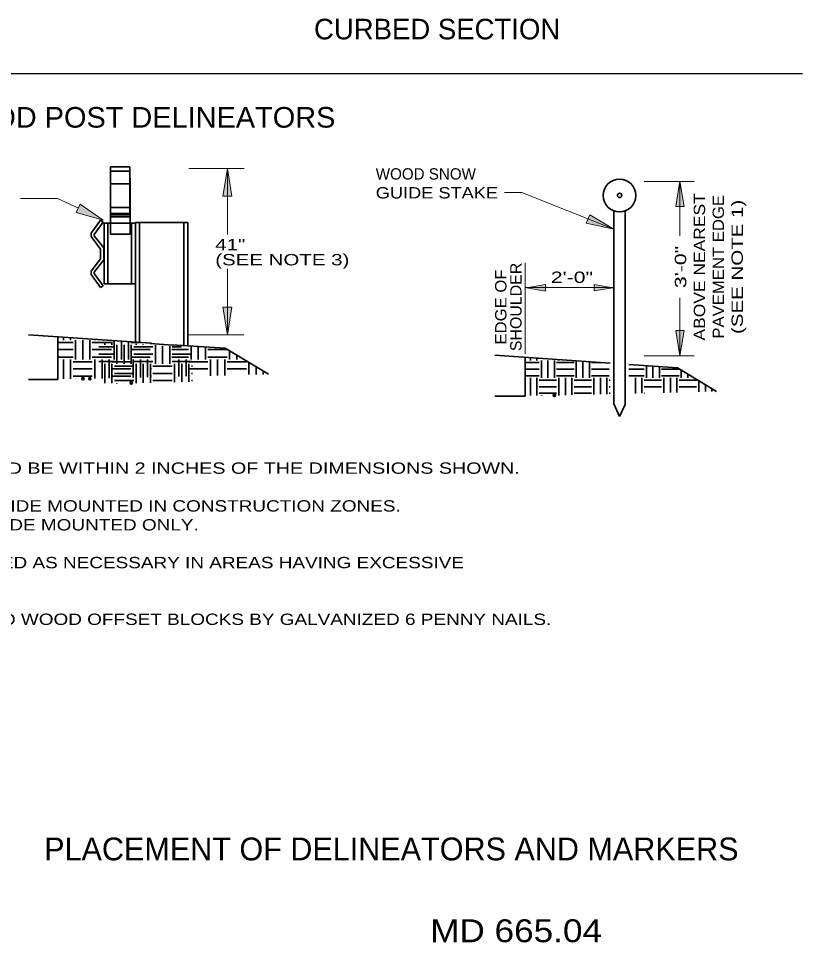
# Model space of a CAD drawing. Extents: x 2147527.1 to 2147534.3, y 2147768.5 to 2147778.6.
# Drawn here: x 2147530.091 to 2147534.243, y 2147768.504 to 2147773.395 of the extents above; entities that cross this region are included whole.
import ezdxf
from ezdxf.enums import TextEntityAlignment as Align

# ---------------------------------------------------------------- set-up
doc = ezdxf.new("R2010")
doc.units = 0
doc.header["$LTSCALE"] = 0.024
doc.header["$PDMODE"] = 32
doc.header["$PDSIZE"] = 0.012
for name, color, linetype, lineweight in [('1', 7, 'Continuous', 35), ('10', 7, 'Continuous', 13), ('63', 7, 'Continuous', 35)]:
    doc.layers.add(name, color=color, linetype=linetype, lineweight=lineweight)
doc.layers.add('12', color=7, linetype='Continuous')
doc.layers.add('13', color=7, linetype='Continuous')

msp = doc.modelspace()

# ---------------------------------------------------------------- hatches: boundary and pattern name
at = {"layer": '10'}
for points in [[(2147531.221, 2147772.454), (2147531.173, 2147772.454), (2147531.197, 2147772.6)], [(2147533.616, 2147772.4), (2147533.572, 2147772.4), (2147533.594, 2147772.533)], [(2147530.397, 2147772.367), (2147530.418, 2147772.412), (2147530.54, 2147772.327)], [(2147533.098, 2147772.311), (2147533.116, 2147772.356), (2147533.243, 2147772.279)], [(2147532.882, 2147771.952), (2147532.882, 2147771.986), (2147532.782, 2147771.969)], [(2147533.139, 2147771.953), (2147533.139, 2147771.986), (2147533.239, 2147771.969)], [(2147531.221, 2147771.866), (2147531.173, 2147771.866), (2147531.197, 2147771.72)], [(2147533.616, 2147771.743), (2147533.572, 2147771.743), (2147533.594, 2147771.61)]]:
    msp.add_hatch(color=256, dxfattribs=at).paths.add_polyline_path(points)

# ---------------------------------------------------------------- linework, layer by layer
at = {"layer": '1'}
for p, q in [((2147530.578, 2147772.61), (2147530.578, 2147772.345)), ((2147530.578, 2147772.61), (2147530.681, 2147772.61)), ((2147530.681, 2147772.587), (2147530.578, 2147772.587)), ((2147530.681, 2147772.345), (2147530.681, 2147772.61)), ((2147530.578, 2147772.254), (2147530.578, 2147772.549)), ((2147530.578, 2147772.519), (2147530.682, 2147772.519)), ((2147530.682, 2147772.549), (2147530.682, 2147772.254)), ((2147530.578, 2147772.394), (2147530.681, 2147772.394)), ((2147533.243, 2147772.377), (2147533.243, 2147771.355)), ((2147533.303, 2147772.377), (2147533.303, 2147771.351)), ((2147530.526, 2147772.327), (2147530.54, 2147772.317)), ((2147530.578, 2147772.362), (2147530.682, 2147772.362)), ((2147530.578, 2147772.356), (2147530.682, 2147772.356)), ((2147530.578, 2147772.344), (2147530.682, 2147772.344)), ((2147530.545, 2147772.314), (2147530.544, 2147771.991)), ((2147530.71, 2147772.311), (2147530.545, 2147772.311)), ((2147530.565, 2147772.314), (2147530.564, 2147771.991)), ((2147530.69, 2147772.313), (2147530.69, 2147771.99)), ((2147530.71, 2147772.314), (2147530.71, 2147771.682)), ((2147530.71, 2147772.314), (2147530.766, 2147772.314)), ((2147530.71, 2147772.313), (2147530.71, 2147771.99)), ((2147530.731, 2147772.314), (2147530.731, 2147771.68)), ((2147530.735, 2147772.314), (2147530.925, 2147772.314)), ((2147530.926, 2147772.314), (2147530.987, 2147772.314)), ((2147530.967, 2147772.314), (2147530.967, 2147771.664)), ((2147530.987, 2147772.314), (2147530.987, 2147771.662)), ((2147530.682, 2147772.254), (2147530.578, 2147772.254)), ((2147530.526, 2147772.123), (2147530.526, 2147772.149)), ((2147530.543, 2147772.117), (2147530.543, 2147772.149)), ((2147530.476, 2147772.057), (2147530.526, 2147772.123)), ((2147530.492, 2147772.052), (2147530.543, 2147772.117)), ((2147530.476, 2147772.039), (2147530.476, 2147772.057)), ((2147530.526, 2147771.97), (2147530.476, 2147772.039)), ((2147530.492, 2147772.045), (2147530.492, 2147772.052)), ((2147530.54, 2147771.98), (2147530.492, 2147772.045)), ((2147530.71, 2147771.99), (2147530.544, 2147771.991)), ((2147530.54, 2147771.98), (2147530.526, 2147771.97)), ((2147530.144, 2147771.721), (2147530.795, 2147771.676)), ((2147530.299, 2147771.71), (2147530.299, 2147771.484)), ((2147530.33, 2147771.692), (2147530.33, 2147771.708)), ((2147530.367, 2147771.692), (2147530.367, 2147771.705)), ((2147530.393, 2147771.59), (2147530.393, 2147771.692)), ((2147530.432, 2147771.59), (2147530.432, 2147771.692)), ((2147530.469, 2147771.59), (2147530.469, 2147771.692)), ((2147530.495, 2147771.692), (2147530.495, 2147771.696)), ((2147530.534, 2147771.692), (2147530.534, 2147771.694)), ((2147530.597, 2147771.59), (2147530.597, 2147771.69)), ((2147530.299, 2147771.68), (2147530.38, 2147771.68)), ((2147530.299, 2147771.642), (2147530.38, 2147771.642)), ((2147530.482, 2147771.68), (2147530.584, 2147771.68)), ((2147530.482, 2147771.642), (2147530.584, 2147771.642)), ((2147530.517, 2147771.656), (2147530.599, 2147771.656)), ((2147530.548, 2147771.668), (2147530.548, 2147771.684)), ((2147530.586, 2147771.668), (2147530.586, 2147771.682)), ((2147530.612, 2147771.567), (2147530.612, 2147771.668)), ((2147530.636, 2147771.59), (2147530.636, 2147771.686)), ((2147530.65, 2147771.567), (2147530.65, 2147771.668)), ((2147530.673, 2147771.59), (2147530.673, 2147771.684)), ((2147530.686, 2147771.68), (2147530.737, 2147771.68)), ((2147530.686, 2147771.642), (2147530.788, 2147771.642)), ((2147530.688, 2147771.567), (2147530.688, 2147771.668)), ((2147530.701, 2147771.656), (2147530.803, 2147771.656)), ((2147530.714, 2147771.668), (2147530.714, 2147771.673)), ((2147530.752, 2147771.668), (2147530.752, 2147771.67)), ((2147530.788, 2147771.675), (2147530.909, 2147771.666)), ((2147530.816, 2147771.567), (2147530.816, 2147771.666)), ((2147530.854, 2147771.567), (2147530.854, 2147771.663)), ((2147530.892, 2147771.567), (2147530.892, 2147771.66)), ((2147530.903, 2147771.668), (2147531.186, 2147771.649)), ((2147530.903, 2147771.642), (2147530.992, 2147771.642)), ((2147530.905, 2147771.656), (2147530.955, 2147771.656)), ((2147531.005, 2147771.59), (2147531.005, 2147771.661)), ((2147531.043, 2147771.59), (2147531.043, 2147771.659)), ((2147531.081, 2147771.59), (2147531.081, 2147771.656)), ((2147531.094, 2147771.642), (2147531.196, 2147771.642)), ((2147531.186, 2147771.649), (2147531.415, 2147771.512)), ((2147530.299, 2147771.603), (2147530.38, 2147771.603)), ((2147530.33, 2147771.488), (2147530.33, 2147771.59)), ((2147530.367, 2147771.488), (2147530.367, 2147771.59)), ((2147530.482, 2147771.603), (2147530.584, 2147771.603)), ((2147530.495, 2147771.489), (2147530.495, 2147771.59)), ((2147530.517, 2147771.618), (2147530.599, 2147771.618)), ((2147530.534, 2147771.49), (2147530.534, 2147771.59)), ((2147530.571, 2147771.491), (2147530.571, 2147771.59)), ((2147530.686, 2147771.603), (2147530.788, 2147771.603)), ((2147530.699, 2147771.494), (2147530.699, 2147771.59)), ((2147530.701, 2147771.618), (2147530.803, 2147771.618)), ((2147530.738, 2147771.495), (2147530.738, 2147771.59)), ((2147530.775, 2147771.496), (2147530.775, 2147771.59)), ((2147530.903, 2147771.603), (2147530.992, 2147771.603)), ((2147530.905, 2147771.618), (2147531.007, 2147771.618)), ((2147530.941, 2147771.5), (2147530.941, 2147771.59)), ((2147530.979, 2147771.501), (2147530.979, 2147771.59)), ((2147531.094, 2147771.603), (2147531.196, 2147771.603)), ((2147531.107, 2147771.504), (2147531.107, 2147771.59)), ((2147531.145, 2147771.505), (2147531.145, 2147771.59)), ((2147531.183, 2147771.506), (2147531.183, 2147771.59)), ((2147531.209, 2147771.59), (2147531.209, 2147771.635)), ((2147531.247, 2147771.59), (2147531.247, 2147771.612)), ((2147532.614, 2147771.612), (2147533.225, 2147771.57)), ((2147532.774, 2147771.601), (2147532.774, 2147771.396)), ((2147532.802, 2147771.585), (2147532.802, 2147771.599)), ((2147532.836, 2147771.585), (2147532.836, 2147771.597)), ((2147530.38, 2147771.578), (2147530.482, 2147771.578)), ((2147530.517, 2147771.58), (2147530.599, 2147771.58)), ((2147530.548, 2147771.465), (2147530.548, 2147771.567)), ((2147530.584, 2147771.578), (2147530.686, 2147771.578)), ((2147530.586, 2147771.465), (2147530.586, 2147771.567)), ((2147530.599, 2147771.554), (2147530.701, 2147771.554)), ((2147530.701, 2147771.58), (2147530.803, 2147771.58)), ((2147530.714, 2147771.465), (2147530.714, 2147771.567)), ((2147530.752, 2147771.466), (2147530.752, 2147771.567)), ((2147530.788, 2147771.578), (2147530.795, 2147771.578)), ((2147530.79, 2147771.467), (2147530.79, 2147771.567)), ((2147530.803, 2147771.554), (2147530.905, 2147771.554)), ((2147530.905, 2147771.58), (2147531.007, 2147771.58)), ((2147530.918, 2147771.47), (2147530.918, 2147771.567)), ((2147530.956, 2147771.471), (2147530.956, 2147771.567)), ((2147530.992, 2147771.578), (2147531.094, 2147771.578)), ((2147530.994, 2147771.472), (2147530.994, 2147771.567)), ((2147531.007, 2147771.554), (2147531.013, 2147771.554)), ((2147531.196, 2147771.578), (2147531.298, 2147771.578)), ((2147531.311, 2147771.51), (2147531.311, 2147771.574)), ((2147531.349, 2147771.51), (2147531.349, 2147771.551)), ((2147532.774, 2147771.574), (2147532.848, 2147771.574)), ((2147532.86, 2147771.492), (2147532.86, 2147771.585)), ((2147532.895, 2147771.492), (2147532.895, 2147771.585)), ((2147532.929, 2147771.492), (2147532.929, 2147771.585)), ((2147532.941, 2147771.574), (2147533.033, 2147771.574)), ((2147532.953, 2147771.585), (2147532.953, 2147771.589)), ((2147532.987, 2147771.585), (2147532.987, 2147771.586)), ((2147533.045, 2147771.492), (2147533.045, 2147771.583)), ((2147533.08, 2147771.492), (2147533.08, 2147771.58)), ((2147533.114, 2147771.492), (2147533.114, 2147771.578)), ((2147533.126, 2147771.574), (2147533.172, 2147771.574)), ((2147533.323, 2147771.563), (2147533.581, 2147771.545)), ((2147533.416, 2147771.492), (2147533.416, 2147771.557)), ((2147533.451, 2147771.492), (2147533.451, 2147771.555)), ((2147533.485, 2147771.492), (2147533.485, 2147771.552)), ((2147533.581, 2147771.545), (2147533.788, 2147771.421)), ((2147530.38, 2147771.54), (2147530.482, 2147771.54)), ((2147530.38, 2147771.501), (2147530.482, 2147771.501)), ((2147530.584, 2147771.54), (2147530.686, 2147771.54)), ((2147530.584, 2147771.501), (2147530.686, 2147771.501)), ((2147530.599, 2147771.516), (2147530.701, 2147771.516)), ((2147530.788, 2147771.54), (2147530.795, 2147771.54)), ((2147530.788, 2147771.501), (2147530.795, 2147771.501)), ((2147530.803, 2147771.516), (2147530.905, 2147771.516)), ((2147530.992, 2147771.54), (2147531.094, 2147771.54)), ((2147530.992, 2147771.501), (2147530.994, 2147771.501)), ((2147531.007, 2147771.516), (2147531.013, 2147771.516)), ((2147531.196, 2147771.54), (2147531.298, 2147771.54)), ((2147531.386, 2147771.511), (2147531.386, 2147771.528)), ((2147532.774, 2147771.539), (2147532.848, 2147771.539)), ((2147532.774, 2147771.504), (2147532.848, 2147771.504)), ((2147532.802, 2147771.4), (2147532.802, 2147771.492)), ((2147532.836, 2147771.4), (2147532.836, 2147771.492)), ((2147532.941, 2147771.539), (2147533.033, 2147771.539)), ((2147532.941, 2147771.504), (2147533.033, 2147771.504)), ((2147532.953, 2147771.4), (2147532.953, 2147771.492)), ((2147532.987, 2147771.401), (2147532.987, 2147771.492)), ((2147533.022, 2147771.402), (2147533.022, 2147771.492)), ((2147533.126, 2147771.539), (2147533.219, 2147771.539)), ((2147533.126, 2147771.504), (2147533.219, 2147771.504)), ((2147533.138, 2147771.405), (2147533.138, 2147771.492)), ((2147533.173, 2147771.406), (2147533.173, 2147771.492)), ((2147533.207, 2147771.406), (2147533.207, 2147771.492)), ((2147533.323, 2147771.539), (2147533.404, 2147771.539)), ((2147533.323, 2147771.504), (2147533.404, 2147771.504)), ((2147533.358, 2147771.41), (2147533.358, 2147771.492)), ((2147533.392, 2147771.412), (2147533.392, 2147771.492)), ((2147533.497, 2147771.539), (2147533.589, 2147771.539)), ((2147533.497, 2147771.504), (2147533.589, 2147771.504)), ((2147533.508, 2147771.414), (2147533.508, 2147771.492)), ((2147533.543, 2147771.415), (2147533.543, 2147771.492)), ((2147533.577, 2147771.416), (2147533.577, 2147771.492)), ((2147533.601, 2147771.492), (2147533.601, 2147771.533)), ((2147533.636, 2147771.492), (2147533.636, 2147771.512)), ((2147530.299, 2147771.484), (2147530.144, 2147771.484)), ((2147530.393, 2147771.487), (2147530.393, 2147771.488)), ((2147530.599, 2147771.478), (2147530.701, 2147771.478)), ((2147530.612, 2147771.463), (2147530.612, 2147771.465)), ((2147530.65, 2147771.464), (2147530.65, 2147771.465)), ((2147530.803, 2147771.478), (2147530.905, 2147771.478)), ((2147531.007, 2147771.478), (2147531.013, 2147771.478)), ((2147532.848, 2147771.481), (2147532.941, 2147771.481)), ((2147532.848, 2147771.446), (2147532.941, 2147771.446)), ((2147533.033, 2147771.481), (2147533.126, 2147771.481)), ((2147533.033, 2147771.446), (2147533.126, 2147771.446)), ((2147533.219, 2147771.481), (2147533.225, 2147771.481)), ((2147533.219, 2147771.446), (2147533.225, 2147771.446)), ((2147533.404, 2147771.481), (2147533.497, 2147771.481)), ((2147533.404, 2147771.446), (2147533.497, 2147771.446)), ((2147533.589, 2147771.481), (2147533.682, 2147771.481)), ((2147533.589, 2147771.446), (2147533.682, 2147771.446)), ((2147533.694, 2147771.419), (2147533.694, 2147771.477)), ((2147533.729, 2147771.42), (2147533.729, 2147771.457)), ((2147532.774, 2147771.396), (2147532.614, 2147771.396)), ((2147532.848, 2147771.412), (2147532.941, 2147771.412)), ((2147532.86, 2147771.398), (2147532.86, 2147771.4)), ((2147532.895, 2147771.399), (2147532.895, 2147771.4)), ((2147533.033, 2147771.412), (2147533.126, 2147771.412)), ((2147533.219, 2147771.412), (2147533.225, 2147771.412)), ((2147533.404, 2147771.412), (2147533.406, 2147771.412)), ((2147533.763, 2147771.42), (2147533.763, 2147771.436)), ((2147533.243, 2147771.355), (2147533.274, 2147771.288)), ((2147533.274, 2147771.288), (2147533.303, 2147771.351))]:
    msp.add_line(p, q, dxfattribs=at)
at = {"layer": '1', "lineweight": 13}
msp.add_line((2147530.992, 2147771.72), (2147531.285, 2147771.72), dxfattribs=at)
at = {"layer": '1'}
for points in [[(2147530.526, 2147772.327), (2147530.476, 2147772.258), (2147530.476, 2147772.24), (2147530.526, 2147772.174), (2147530.526, 2147772.149)], [(2147530.54, 2147772.317), (2147530.492, 2147772.252), (2147530.492, 2147772.245), (2147530.543, 2147772.18), (2147530.543, 2147772.149)]]:
    msp.add_lwpolyline(points, dxfattribs=at)
for radius in [0.0864, 0.0114]:
    msp.add_circle((2147533.2739, 2147772.4579), radius, dxfattribs=at)
for p in [(2147530.432, 2147771.488), (2147530.469, 2147771.488), (2147530.688, 2147771.465), (2147532.929, 2147771.4)]:
    msp.add_point(p, dxfattribs=at)
at = {"layer": '10'}
for p, q in [((2147530.994, 2147772.6), (2147531.287, 2147772.6)), ((2147531.197, 2147772.6), (2147531.197, 2147772.251)), ((2147533.404, 2147772.532), (2147533.67, 2147772.532)), ((2147533.594, 2147772.532), (2147533.594, 2147772.245)), ((2147532.756, 2147772.473), (2147532.664, 2147772.473)), ((2147533.243, 2147772.279), (2147532.756, 2147772.473)), ((2147530.297, 2147772.442), (2147530.101, 2147772.442)), ((2147530.408, 2147772.39), (2147530.297, 2147772.442)), ((2147532.775, 2147772.102), (2147532.775, 2147771.619)), ((2147531.197, 2147772.069), (2147531.197, 2147771.72)), ((2147532.775, 2147771.97), (2147533.243, 2147771.97)), ((2147533.594, 2147771.61), (2147533.594, 2147771.916)), ((2147533.404, 2147771.61), (2147533.67, 2147771.61))]:
    msp.add_line(p, q, dxfattribs=at)
for points in [[(2147531.221, 2147772.454), (2147531.173, 2147772.454), (2147531.197, 2147772.6)], [(2147533.616, 2147772.4), (2147533.572, 2147772.4), (2147533.594, 2147772.533)], [(2147530.397, 2147772.367), (2147530.418, 2147772.412), (2147530.54, 2147772.327)], [(2147533.098, 2147772.311), (2147533.116, 2147772.356), (2147533.243, 2147772.279)], [(2147532.882, 2147771.952), (2147532.882, 2147771.986), (2147532.782, 2147771.969)], [(2147533.139, 2147771.953), (2147533.139, 2147771.986), (2147533.239, 2147771.969)], [(2147531.221, 2147771.866), (2147531.173, 2147771.866), (2147531.197, 2147771.72)], [(2147533.616, 2147771.743), (2147533.572, 2147771.743), (2147533.594, 2147771.61)]]:
    msp.add_lwpolyline(points, close=True, dxfattribs=at)
at = {"layer": '63', "lineweight": 25}
msp.add_line((2147527.127, 2147773.104), (2147534.243, 2147773.104), dxfattribs=at)

# ---------------------------------------------------------------- texts
at = {"layer": '12'}
msp.add_text('CURBED SECTION', height=0.109, dxfattribs=at).set_placement((2147531.656, 2147773.284))
at = {"layer": '12', "width": 1.05}
msp.add_text('PLACEMENT OF W-BEAM & WOOD POST DELINEATORS', height=0.109, dxfattribs=at).set_placement((2147527.645, 2147772.817))
at = {"layer": '13'}
for s, height, p in [('WOOD SNOW', 0.06, (2147531.983, 2147772.542)), ('PLACEMENT OF DELINEATORS AND MARKERS', 0.121, (2147530.227, 2147768.939))]:
    msp.add_text(s, height=height, dxfattribs=at).set_placement(p)
for s, height, width, p in [('GUIDE STAKE', 0.06, 1.2, (2147531.983, 2147772.442)), ('41"', 0.06, 1.35, (2147531.133, 2147772.168)), ('(SEE NOTE 3)', 0.06, 1.35, (2147531.133, 2147772.088)), ('2\'-0"', 0.06, 1.4, (2147532.91, 2147771.995)), ('1. THE HEIGHT OF THE DELINEATOR SHOULD BE WITHIN 2 INCHES OF THE DIMENSIONS SHOWN.', 0.06, 1.3, (2147527.791, 2147770.985)), ('2. BARRIER MARKERS SHOULD BE TOP AND SIDE MOUNTED IN CONSTRUCTION ZONES.', 0.06, 1.25, (2147527.791, 2147770.785)), ('   PERMANENT INSTALLATIONS SHOULD BE SIDE MOUNTED ONLY.', 0.06, 1.25, (2147527.791, 2147770.685)), ('3. HEIGHT OF DELINEATOR MAY BE INCREASED AS NECESSARY IN AREAS HAVING EXCESSIVE', 0.06, 1.25, (2147527.791, 2147770.485)), ('4. W-BEAM MARKERS SHALL BE FASTENED TO WOOD OFFSET BLOCKS BY GALVANIZED 6 PENNY NAILS.', 0.06, 1.25, (2147527.791, 2147770.185)), ('MD 665.04', 0.121, 1.15, (2147532.271, 2147768.506))]:
    msp.add_text(s, height=height, dxfattribs=dict(at, width=width)).set_placement(p)
for s, width, p in [('ABOVE NEAREST', 1.15, (2147533.727, 2147772.08)), ('PAVEMENT EDGE', 1.1, (2147533.827, 2147772.0805)), ('(SEE NOTE 1)', 1.35, (2147533.927, 2147772.08)), ('3\'-0"', 1.4, (2147533.627, 2147772.0795)), ('SHOULDER', 1.05, (2147532.755, 2147771.868)), ('EDGE OF', 1.1, (2147532.675, 2147771.8675))]:
    msp.add_text(s, height=0.06, rotation=90, dxfattribs=dict(at, width=width)).set_placement(p, align=Align.CENTER)

doc.saveas('drawing.dxf')
